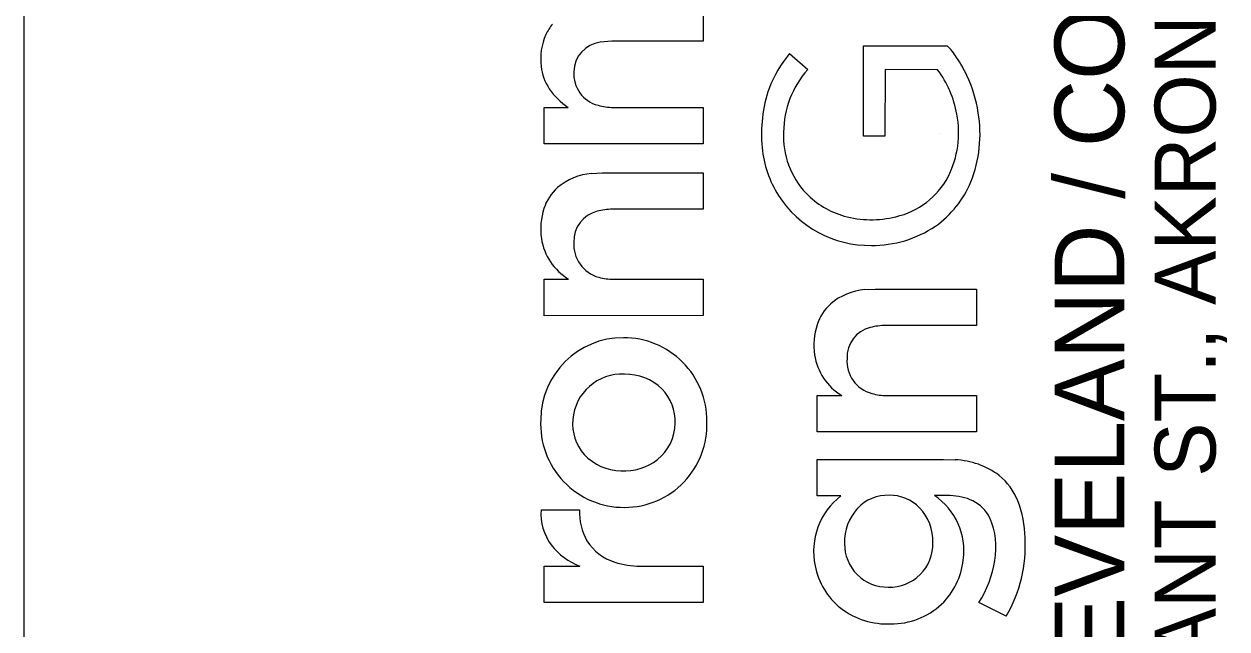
# Model space of a CAD drawing. Extents: x -6.7 to 34, y -3.7 to 22.
# Drawn here: x 32 to 32.984, y 3.594 to 4.09 of the extents above; entities that cross this region are included whole.
import ezdxf

# ---------------------------------------------------------------- set-up
doc = ezdxf.new("R2010")
doc.units = 0
doc.layers.add('SH_Border', color=7, linetype='Continuous')
doc.layers.add('SH_Named_Boundary', color=7, linetype='Continuous')

msp = doc.modelspace()

# ---------------------------------------------------------------- linework, layer by layer
at = {"layer": 'SH_Border'}
msp.add_line((32, 0.5), (32, 21.5), dxfattribs=at)
at = {"layer": 'SH_Named_Boundary'}
for p, q in [((32.55571, 4.10548), (32.55571, 4.07568)), ((32.4809, 4.07567), (32.47143, 4.07474)), ((32.55571, 4.07568), (32.4809, 4.07567)), ((32.62636, 4.06548), (32.64114, 4.05241)), ((32.6868, 4.07185), (32.75516, 4.07192)), ((32.6868, 3.99778), (32.6868, 4.07185)), ((32.70448, 4.05241), (32.70432, 3.99775)), ((32.74737, 4.05227), (32.70448, 4.05241)), ((32.42542, 3.99152), (32.42545, 4.02138)), ((32.42545, 4.02138), (32.44515, 4.02138)), ((32.48206, 4.02138), (32.55571, 4.02136)), ((32.55571, 4.02136), (32.55571, 3.99156)), ((32.70432, 3.99775), (32.6868, 3.99778)), ((32.75, 4), (32.75, 4)), ((32.55571, 3.99156), (32.42542, 3.99152)), ((32.46439, 3.96736), (32.47289, 3.96783)), ((32.47289, 3.96783), (32.55571, 3.96783)), ((32.55571, 3.96783), (32.55571, 3.93804)), ((32.55571, 3.93804), (32.4814, 3.93796)), ((32.42542, 3.88066), (32.44552, 3.88071)), ((32.42542, 3.85086), (32.42542, 3.88066)), ((32.48222, 3.88071), (32.55569, 3.88071)), ((32.55569, 3.88071), (32.55571, 3.85096)), ((32.68784, 3.8722), (32.69634, 3.87266)), ((32.69634, 3.87266), (32.77916, 3.87266)), ((32.77916, 3.87266), (32.77917, 3.84287)), ((32.55571, 3.85096), (32.42542, 3.85086)), ((32.77917, 3.84287), (32.70485, 3.8428)), ((32.64888, 3.7855), (32.66897, 3.78555)), ((32.64888, 3.75569), (32.64888, 3.7855)), ((32.70568, 3.78555), (32.77915, 3.78555)), ((32.77915, 3.78555), (32.77917, 3.75579)), ((32.77917, 3.75579), (32.64888, 3.75569)), ((32.6489, 3.70336), (32.64889, 3.73322)), ((32.64889, 3.73322), (32.75236, 3.73322)), ((32.75236, 3.73322), (32.76191, 3.73285)), ((32.66836, 3.70336), (32.6489, 3.70336)), ((32.75763, 3.70356), (32.74487, 3.70361)), ((32.42299, 3.69193), (32.45454, 3.69193)), ((32.42542, 3.64577), (32.45473, 3.64579)), ((32.42542, 3.61593), (32.42542, 3.64577)), ((32.50413, 3.64581), (32.55571, 3.64573)), ((32.55571, 3.64573), (32.55565, 3.61593)), ((32.55565, 3.61593), (32.42542, 3.61593)), ((32.8036, 3.60491), (32.7812, 3.61598))]:
    msp.add_line(p, q, dxfattribs=at)
for points in [[(32.48218, 4.10553), (32.55571, 4.10548), (32.55571, 4.07568), (32.4809, 4.07567), (32.47143, 4.07474)], [(32.62636, 4.06548), (32.64114, 4.05241)], [(32.74737, 4.05227), (32.70448, 4.05241), (32.70432, 3.99775), (32.6868, 3.99778), (32.6868, 4.07185), (32.75516, 4.07192)], [(32.42542, 3.99152), (32.42545, 4.02138), (32.44515, 4.02138)], [(32.48206, 4.02138), (32.55571, 4.02136), (32.55571, 3.99156), (32.42542, 3.99152)], [(32.46439, 3.96736), (32.47289, 3.96783), (32.55571, 3.96783), (32.55571, 3.93804), (32.4814, 3.93796)], [(32.42542, 3.85086), (32.42542, 3.88066), (32.44552, 3.88071)], [(32.48222, 3.88071), (32.55569, 3.88071), (32.55571, 3.85096), (32.42542, 3.85086)], [(32.68784, 3.8722), (32.69634, 3.87266), (32.77916, 3.87266), (32.77917, 3.84287), (32.70485, 3.8428)], [(32.64888, 3.75569), (32.64888, 3.7855), (32.66897, 3.78555)], [(32.70568, 3.78555), (32.77915, 3.78555), (32.77917, 3.75579), (32.64888, 3.75569)], [(32.66836, 3.70336), (32.6489, 3.70336), (32.64889, 3.73322), (32.75236, 3.73322), (32.76191, 3.73285)], [(32.75763, 3.70356), (32.74487, 3.70361)], [(32.42299, 3.69193), (32.45454, 3.69193)], [(32.50413, 3.64581), (32.55571, 3.64573), (32.55565, 3.61593), (32.42542, 3.61593)], [(32.42542, 3.61593), (32.42542, 3.64577), (32.45473, 3.64579)], [(32.8036, 3.60491), (32.7812, 3.61598)]]:
    msp.add_lwpolyline(points, dxfattribs=at)
for centre, radius, start, end in [((32.46194, 4.06452), 0.03875, 139.52447, 154.84698), ((32.46194, 4.06452), 0.03875, 139.52447, 154.84698), ((32.47144, 4.0612), 0.04877, 156.06382, 187.3493), ((32.47144, 4.0612), 0.04877, 156.06382, 187.3493), ((32.47421, 4.05056), 0.02434, 96.5532, 179.94902), ((32.47421, 4.05056), 0.02434, 96.5532, 179.94902), ((32.70163, 4.00187), 0.09855, 139.79476, 159.13696), ((32.70163, 4.00187), 0.09855, 139.79476, 159.13696), ((32.72498, 4.03937), 0.04438, 30.98913, 47.16099), ((32.72498, 4.03937), 0.04438, 30.98913, 47.16099), ((32.46461, 4.05974), 0.04181, 186.5579, 213.38846), ((32.46461, 4.05974), 0.04181, 186.5579, 213.38846), ((32.67091, 4.00018), 0.11106, 25.30315, 33.96179), ((32.67091, 4.00018), 0.11106, 25.30315, 33.96179), ((32.47608, 4.04863), 0.02628, 175.722, 255.78627), ((32.47608, 4.04863), 0.02628, 175.722, 255.78627), ((32.69899, 4.00079), 0.07753, 138.25804, 179.70064), ((32.69899, 4.00079), 0.07753, 138.25804, 179.70064), ((32.67889, 4.00099), 0.08556, 10.07509, 36.83189), ((32.67889, 4.00099), 0.08556, 10.07509, 36.83189), ((32.6704, 3.99987), 0.11166, 8.80339, 25.33484), ((32.6704, 3.99987), 0.11166, 8.80339, 25.33484), ((32.47886, 4.07078), 0.0598, 214.70433, 235.68724), ((32.47886, 4.07078), 0.0598, 214.70433, 235.68724), ((32.7187, 3.99968), 0.11536, 161.14379, 185.62812), ((32.7187, 3.99968), 0.11536, 161.14379, 185.62812), ((32.48195, 4.06518), 0.0438, 253.66719, 270.14979), ((32.48195, 4.06518), 0.0438, 253.66719, 270.14979), ((32.68425, 4.00057), 0.08036, 333.46689, 11.03668), ((32.68425, 4.00057), 0.08036, 333.46689, 11.03668), ((32.67564, 3.99977), 0.10649, 338.28866, 9.28548), ((32.67564, 3.99977), 0.10649, 338.28866, 9.28548), ((32.68811, 3.99732), 0.06676, 176.66577, 223.6912), ((32.68811, 3.99732), 0.06676, 176.66577, 223.6912), ((32.69336, 3.99699), 0.08987, 185.50773, 212.01294), ((32.69336, 3.99699), 0.08987, 185.50773, 212.01294), ((32.46871, 3.91767), 0.04988, 94.97056, 130.22484), ((32.46871, 3.91767), 0.04988, 94.97056, 130.22484), ((32.69868, 3.99547), 0.0652, 282.88151, 331.81475), ((32.69868, 3.99547), 0.0652, 282.88151, 331.81475), ((32.69835, 3.99168), 0.08241, 305.03061, 337.67573), ((32.69835, 3.99168), 0.08241, 305.03061, 337.67573), ((32.46348, 3.92602), 0.04016, 132.22383, 161.68229), ((32.46348, 3.92602), 0.04016, 132.22383, 161.68229), ((32.69211, 3.99748), 0.08908, 212.70222, 270.71399), ((32.69211, 3.99748), 0.08908, 212.70222, 270.71399), ((32.69045, 4.00011), 0.07039, 224.02147, 253.88), ((32.69045, 4.00011), 0.07039, 224.02147, 253.88), ((32.47872, 3.92158), 0.05602, 162.27398, 187.79173), ((32.47872, 3.92158), 0.05602, 162.27398, 187.79173), ((32.48108, 3.89196), 0.04601, 89.60515, 105.33026), ((32.48108, 3.89196), 0.04601, 89.60515, 105.33026), ((32.47482, 3.91206), 0.02498, 103.68683, 182.21395), ((32.47482, 3.91206), 0.02498, 103.68683, 182.21395), ((32.69318, 4.01254), 0.08309, 254.45353, 283.9512), ((32.69318, 4.01254), 0.08309, 254.45353, 283.9512), ((32.69429, 3.99979), 0.09138, 269.3273, 304.19632), ((32.69429, 3.99979), 0.09138, 269.3273, 304.19632), ((32.47027, 3.92141), 0.04763, 188.96462, 238.69865), ((32.47027, 3.92141), 0.04763, 188.96462, 238.69865), ((32.47735, 3.90897), 0.02757, 175.58441, 255.13816), ((32.47735, 3.90897), 0.02757, 175.58441, 255.13816), ((32.48183, 3.92286), 0.04215, 254.08913, 270.52838), ((32.48183, 3.92286), 0.04215, 254.08913, 270.52838), ((32.69216, 3.82251), 0.04988, 94.97056, 130.22484), ((32.69216, 3.82251), 0.04988, 94.97056, 130.22484), ((32.68694, 3.83085), 0.04016, 132.22383, 161.68229), ((32.68694, 3.83085), 0.04016, 132.22383, 161.68229), ((32.70217, 3.82642), 0.05602, 162.27398, 187.79173), ((32.70217, 3.82642), 0.05602, 162.27398, 187.79173), ((32.69828, 3.81689), 0.02498, 103.68683, 182.21395), ((32.69828, 3.81689), 0.02498, 103.68683, 182.21395), ((32.70453, 3.79679), 0.04601, 89.60515, 105.33026), ((32.70453, 3.79679), 0.04601, 89.60515, 105.33026), ((32.49014, 3.76543), 0.0674, 89.84756, 179.64047), ((32.49014, 3.76543), 0.0674, 89.84756, 179.64047), ((32.49057, 3.76474), 0.0681, 359.54009, 90.21138), ((32.49057, 3.76474), 0.0681, 359.54009, 90.21138), ((32.69372, 3.82624), 0.04763, 188.96462, 238.69865), ((32.69372, 3.82624), 0.04763, 188.96462, 238.69865), ((32.7008, 3.81381), 0.02757, 175.58441, 255.13816), ((32.7008, 3.81381), 0.02757, 175.58441, 255.13816), ((32.48923, 3.76263), 0.0404, 87.04809, 175.57259), ((32.48923, 3.76263), 0.0404, 87.04809, 175.57259), ((32.49204, 3.75999), 0.04299, 45.84264, 90.98008), ((32.49204, 3.75999), 0.04299, 45.84264, 90.98008), ((32.49458, 3.76421), 0.03821, 357.88569, 44.15902), ((32.49458, 3.76421), 0.03821, 357.88569, 44.15902), ((32.70529, 3.82769), 0.04215, 254.08913, 270.52838), ((32.70529, 3.82769), 0.04215, 254.08913, 270.52838), ((32.49083, 3.76209), 0.06819, 176.8344, 270.40384), ((32.49083, 3.76209), 0.06819, 176.8344, 270.40384), ((32.48729, 3.7625), 0.03848, 175.15378, 221.14706), ((32.48729, 3.7625), 0.03848, 175.15378, 221.14706), ((32.49123, 3.76139), 0.06749, 270.06243, 2.37759), ((32.49123, 3.76139), 0.06749, 270.06243, 2.37759), ((32.49446, 3.76318), 0.0383, 308.28936, 359.43468), ((32.49446, 3.76318), 0.0383, 308.28936, 359.43468), ((32.48919, 3.76607), 0.04228, 223.09994, 268.80895), ((32.48919, 3.76607), 0.04228, 223.09994, 268.80895), ((32.49096, 3.7679), 0.04418, 266.56515, 308.06078), ((32.49096, 3.7679), 0.04418, 266.56515, 308.06078), ((32.75907, 3.66789), 0.06503, 53.40344, 87.49062), ((32.75907, 3.66789), 0.06503, 53.40344, 87.49062), ((32.76517, 3.68039), 0.05141, 21.60748, 50.5577), ((32.76517, 3.68039), 0.05141, 21.60748, 50.5577), ((32.70292, 3.65813), 0.05692, 127.37482, 192.22468), ((32.70292, 3.65813), 0.05692, 127.37482, 192.22468), ((32.70693, 3.66927), 0.0346, 88.47302, 136.42562), ((32.70693, 3.66927), 0.0346, 88.47302, 136.42562), ((32.70814, 3.66963), 0.03424, 44.27195, 90.47623), ((32.70814, 3.66963), 0.03424, 44.27195, 90.47623), ((32.71421, 3.65829), 0.05472, 352.1125, 55.92295), ((32.71421, 3.65829), 0.05472, 352.1125, 55.92295), ((32.75666, 3.65725), 0.04633, 65.01687, 88.8011), ((32.75666, 3.65725), 0.04633, 65.01687, 88.8011), ((32.46616, 3.68882), 0.04329, 175.87313, 216.34747), ((32.46616, 3.68882), 0.04329, 175.87313, 216.34747), ((32.50087, 3.68948), 0.04639, 176.9688, 209.60636), ((32.50087, 3.68948), 0.04639, 176.9688, 209.60636), ((32.71141, 3.66602), 0.0401, 137.46739, 182.33237), ((32.71141, 3.66602), 0.0401, 137.46739, 182.33237), ((32.70368, 3.666), 0.03996, 358.57141, 43.53765), ((32.70368, 3.666), 0.03996, 358.57141, 43.53765), ((32.7626, 3.67155), 0.03085, 26.26808, 63.80301), ((32.7626, 3.67155), 0.03085, 26.26808, 63.80301), ((32.73069, 3.66714), 0.08835, 1.15143, 21.3627), ((32.73069, 3.66714), 0.08835, 1.15143, 21.3627), ((32.73565, 3.66154), 0.05953, 349.30734, 23.43071), ((32.73565, 3.66154), 0.05953, 349.30734, 23.43071), ((32.47466, 3.69716), 0.05511, 218.09809, 248.7907), ((32.47466, 3.69716), 0.05511, 218.09809, 248.7907), ((32.49514, 3.68814), 0.04079, 211.94466, 253.2028), ((32.49514, 3.68814), 0.04079, 211.94466, 253.2028), ((32.70645, 3.6637), 0.03511, 178.88208, 271.08374), ((32.70645, 3.6637), 0.03511, 178.88208, 271.08374), ((32.70818, 3.66404), 0.03546, 268.27882, 1.55016), ((32.70818, 3.66404), 0.03546, 268.27882, 1.55016), ((32.70538, 3.66244), 0.11383, 329.6388, 3.25998), ((32.70538, 3.66244), 0.11383, 329.6388, 3.25998), ((32.50465, 3.7165), 0.07069, 252.46555, 269.57296), ((32.50465, 3.7165), 0.07069, 252.46555, 269.57296), ((32.70463, 3.65696), 0.05837, 190.75182, 231.28919), ((32.70463, 3.65696), 0.05837, 190.75182, 231.28919), ((32.70988, 3.65708), 0.05887, 313.74196, 353.8554), ((32.70988, 3.65708), 0.05887, 313.74196, 353.8554), ((32.70738, 3.66334), 0.08771, 327.31495, 351.57478), ((32.70738, 3.66334), 0.08771, 327.31495, 351.57478), ((32.70954, 3.65901), 0.06051, 269.6361, 312.70877), ((32.70954, 3.65901), 0.06051, 269.6361, 312.70877), ((32.70632, 3.66112), 0.06269, 232.46061, 272.59022), ((32.70632, 3.66112), 0.06269, 232.46061, 272.59022)]:
    msp.add_arc(centre, radius, start, end, dxfattribs=at)

# ---------------------------------------------------------------- texts
for s, height, p in [('450 GRANT ST., AKRON, OH  44311', 0.0498462, (32.97489, 3.33738)), ('AKRON / CLEVELAND / COLUMBUS', 0.056969, (32.90012, 3.138))]:
    msp.add_text(s, height=height, rotation=90, dxfattribs=at).set_placement(p)

doc.saveas('drawing.dxf')
